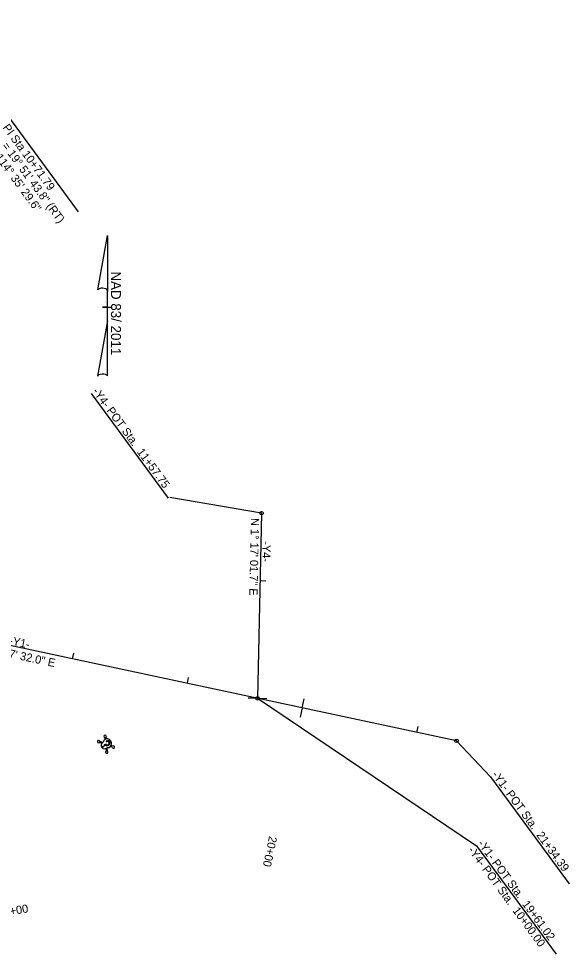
# Model space of a CAD drawing. Extents: x 1762196 to 1766326, y 709922 to 713142.
# Drawn here: x 1764036 to 1764505, y 712112 to 712909 of the extents above; entities that cross this region are included whole.
import ezdxf

# ---------------------------------------------------------------- set-up
doc = ezdxf.new("R2010")
doc.units = 0
for name, color, linetype in [('Prop Dimension', 7, 'Continuous'), ('Prop Horizontal Alignment', 7, 'Continuous'), ('Prop Horizontal Alignment Curve and Spiral Data', 7, 'Continuous'), ('Prop Horizontal Alignment Direction Label', 7, 'Continuous'), ('Prop Horizontal Alignment Station Label', 7, 'Continuous'), ('Prop Horizontal Alignment Tick Label', 7, 'Continuous'), ('Prop Horizontal Alignment Tick Large', 7, 'Continuous'), ('Prop Horizontal Alignment Tick Small', 7, 'Continuous'), ('Prop North Arrow NAD83 for Plan Sheets CELL', 7, 'Continuous')]:
    doc.layers.add(name, color=color, linetype=linetype)

msp = doc.modelspace()

# ---------------------------------------------------------------- linework, layer by layer
at = {"layer": 'Prop Dimension'}
for p, q in [((1764109.03, 712296.23), (1764109.18, 712294.69)), ((1764110, 712296.33), (1764110.12, 712295.08)), ((1764106.67, 712291.22), (1764104.46, 712292.03)), ((1764107.33, 712292.02), (1764104.79, 712292.95)), ((1764108.91, 712289.97), (1764108.48, 712289.64)), ((1764108.48, 712289.64), (1764108.86, 712289.15)), ((1764108.96, 712289.9), (1764108.53, 712289.57)), ((1764109.02, 712289.83), (1764108.59, 712289.5)), ((1764109.07, 712289.76), (1764108.64, 712289.43)), ((1764109.13, 712289.69), (1764108.7, 712289.36)), ((1764109.18, 712289.62), (1764108.75, 712289.29)), ((1764109.24, 712289.55), (1764108.81, 712289.22)), ((1764109.29, 712289.48), (1764108.86, 712289.15)), ((1764110.18, 712293.11), (1764110.56, 712292.62)), ((1764110.34, 712290.69), (1764110.34, 712290.69)), ((1764115.38, 712288.05), (1764113.93, 712288.58)), ((1764115.72, 712288.96), (1764114.54, 712289.39)), ((1764109.95, 712287), (1764110.18, 712284.66)), ((1764110.88, 712287.45), (1764111.15, 712284.76))]:
    msp.add_line(p, q, dxfattribs=at)
for radius in [0.443, 0.345, 0.244, 0.146, 0.0472]:
    msp.add_circle((1764107.62, 712288.55), radius, dxfattribs=at)
for centre, start, end in [((1764109.42, 712297.19), 303.725, 247.63356), ((1764103.76, 712292.8), 8.02122, 311.92977), ((1764116.41, 712288.19), 188.02122, 131.92977), ((1764110.75, 712283.8), 123.725, 67.63356)]:
    msp.add_arc(centre, 1.04, start, end, dxfattribs=at)
for centre, major_axis, ratio, start_param, end_param in [((1764109.55, 712290.08), (-3.07, -2.38), 0.752542, 4.722735, 7.843636), ((1764111.31, 712291.44), (2.38, -3.07), 0.885014, 5.564242, 10.143721), ((1764109.83, 712288.78), (1.32, 1.03), 0.9, 0.426026, 1.570796), ((1764109.83, 712288.78), (1.24, 0.97), 0.9, 0.426026, 1.570796), ((1764109.83, 712288.78), (1.17, 0.91), 0.9, 0.426026, 1.570796), ((1764109.83, 712288.78), (1.09, 0.85), 0.9, 0.426026, 1.570796), ((1764109.83, 712288.78), (1.01, 0.78), 0.9, 0.426026, 1.570796), ((1764109.83, 712288.78), (0.933, 0.724), 0.9, 0.426026, 1.570796), ((1764109.83, 712288.78), (0.855, 0.664), 0.9, 0.426026, 1.570796), ((1764109.83, 712288.78), (0.778, 0.604), 0.9, 0.426026, 1.570796), ((1764111.41, 712291.52), (1.76, 1.37), 0.9, 3.567618, 7.853982), ((1764111.41, 712291.52), (1.68, 1.31), 0.9, 3.567618, 7.853982), ((1764111.41, 712291.52), (1.61, 1.25), 0.9, 3.567618, 7.853982), ((1764111.41, 712291.52), (1.53, 1.19), 0.9, 3.567618, 7.853982), ((1764111.41, 712291.52), (1.45, 1.13), 0.9, 3.567618, 7.853982), ((1764111.41, 712291.52), (1.37, 1.07), 0.9, 3.567618, 7.853982), ((1764111.41, 712291.52), (1.3, 1.01), 0.9, 3.567618, 7.853982), ((1764111.41, 712291.52), (1.22, 0.95), 0.9, 3.567618, 7.853982)]:
    msp.add_ellipse(centre, major_axis=major_axis, ratio=ratio, start_param=start_param, end_param=end_param, dxfattribs=at)
at = {"layer": 'Prop Horizontal Alignment'}
for p, q in [((1764408.68, 712293.5), (1763471.86, 712493.33)), ((1764242.66, 712487.38), (1764239.13, 712329.67))]:
    msp.add_line(p, q, dxfattribs=at)
at = {"layer": 'Prop Horizontal Alignment Curve and Spiral Data'}
msp.add_line((1763965.48, 712908.59), (1764086.47, 712743.96), dxfattribs=at)
at = {"layer": 'Prop Horizontal Alignment Station Label'}
for p, q in [((1764097.53, 712589.26), (1764163.1, 712500.04)), ((1764242.66, 712487.38), (1764164.64, 712500.7)), ((1764239.13, 712329.67), (1764425.73, 712204.08)), ((1764408.68, 712293.5), (1764437.7, 712262.87)), ((1764437.7, 712262.87), (1764504.79, 712171.58)), ((1764425.73, 712204.08), (1764493.69, 712111.62))]:
    msp.add_line(p, q, dxfattribs=at)
for centre in [(1764242.66, 712487.38), (1764239.13, 712329.67), (1764408.68, 712293.5)]:
    msp.add_circle(centre, 1.5, dxfattribs=at)
at = {"layer": 'Prop Horizontal Alignment Tick Large'}
for p, q in [((1764239.13, 712329.67), (1764231.13, 712329.85)), ((1764239.13, 712329.67), (1764247.12, 712329.49)), ((1764277.25, 712321.53), (1764278.92, 712329.36)), ((1764277.25, 712321.53), (1764275.58, 712313.71))]:
    msp.add_line(p, q, dxfattribs=at)
at = {"layer": 'Prop Horizontal Alignment Tick Small'}
for p, q in [((1764246.36, 712429.53), (1764241.37, 712429.64)), ((1764081.65, 712363.26), (1764082.69, 712368.15)), ((1764179.45, 712342.4), (1764180.49, 712347.29)), ((1764375.05, 712300.67), (1764376.09, 712305.56))]:
    msp.add_line(p, q, dxfattribs=at)
at = {"layer": 'Prop North Arrow NAD83 for Plan Sheets CELL'}
for p, q in [((1764103.08, 712677.56), (1764111.28, 712723.91)), ((1764111.33, 712723.91), (1764111.28, 712723.91)), ((1764111.33, 712723.91), (1764111.28, 712723.91)), ((1764111.33, 712723.91), (1764111.33, 712676.11)), ((1764111.33, 712651.31), (1764111.33, 712677.51)), ((1764111.33, 712676.11), (1764111.33, 712677.46)), ((1764107.33, 712662.91), (1764107.28, 712662.91)), ((1764110.88, 712662.91), (1764107.33, 712662.91)), ((1764107.38, 712662.91), (1764115.38, 712662.91)), ((1764111.33, 712651.31), (1764102.98, 712604.06)), ((1764111.38, 712604.26), (1764111.33, 712651.31))]:
    msp.add_line(p, q, dxfattribs=at)
for centre, start_param, end_param in [((1764107.21, 712677.07), 0.216388, 2.908219), ((1764107.21, 712603.9), 0.201328, 3.141593)]:
    msp.add_ellipse(centre, major_axis=(4.23, -0.03), ratio=0.461098, start_param=start_param, end_param=end_param, dxfattribs=at)

# ---------------------------------------------------------------- texts
at = {"layer": 'Prop Horizontal Alignment Curve and Spiral Data'}
for s, p in [('PI Sta 10+71.79', (1764021.69, 712815.76)), ('D = 114%%d 35\' 29.6"', (1764005.18, 712804.46)), ('= 19%%d 51\' 43.8" (RT)', (1764021.08, 712800.2))]:
    msp.add_text(s, height=7, rotation=306.313, dxfattribs=at).set_placement(p)
at = {"layer": 'Prop Horizontal Alignment Direction Label'}
for s, rotation, p in [('N 1%%d 17\' 01.7" E', 268.7162, (1764233.63, 712483.33)), ('-Y4-', 268.7162, (1764243.48, 712463.59)), ('S 77%%d 57\' 32.0" E', 347.95889, (1763996.89, 712371)), ('-Y1- ', 347.86385, (1764027.12, 712375.74))]:
    msp.add_text(s, height=7, rotation=rotation, dxfattribs=at).set_placement(p)
at = {"layer": 'Prop Horizontal Alignment Station Label'}
for s, p in [('-Y4- POT Sta.  11+57.75', (1764098.23, 712591.07)), ('-Y1- POT Sta.  21+34.39', (1764438.5, 712264.57)), ('-Y4- POT Sta.  10+00.00', (1764418.17, 712200.31)), ('-Y1- POT Sta.  19+61.02', (1764426.44, 712205.81))]:
    msp.add_text(s, height=7, rotation=306.31306, dxfattribs=at).set_placement(p)
at = {"layer": 'Prop Horizontal Alignment Tick Label'}
for s, rotation, p in [('20+00', 257.95889, (1764249.17, 712212.69)), ('15+00', 10.02041, (1764018.47, 712142.9))]:
    msp.add_text(s, height=7, rotation=rotation, dxfattribs=at).set_placement(p)
at = {"layer": 'Prop North Arrow NAD83 for Plan Sheets CELL'}
msp.add_text('NAD 83/ 2011', height=8.5, rotation=270, dxfattribs=at).set_placement((1764114.38, 712693.3))

doc.saveas('drawing.dxf')
